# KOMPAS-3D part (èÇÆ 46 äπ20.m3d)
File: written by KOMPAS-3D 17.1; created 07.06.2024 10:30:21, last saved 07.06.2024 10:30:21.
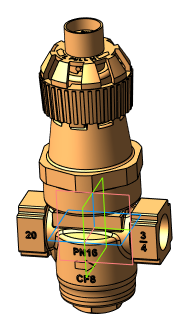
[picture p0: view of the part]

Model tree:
1. Операция без истории:1  (labels: Сталь 20  ГОСТ 1050-2013)

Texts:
  ООО АДЛ Групп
